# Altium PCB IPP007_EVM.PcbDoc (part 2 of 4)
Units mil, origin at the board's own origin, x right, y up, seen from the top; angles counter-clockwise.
Board outline 3500.95 x 3103 mil, 6 copper layers (Top Layer, Int1 (GND), Int2 (Sign), Int3 (Sign), Int4 (GND), Bottom Layer), stack 61.068 mil thick; 257 components, 132 nets, 1052 pads, 535 vias.
Unrouted connection lines stored in the file: 3.
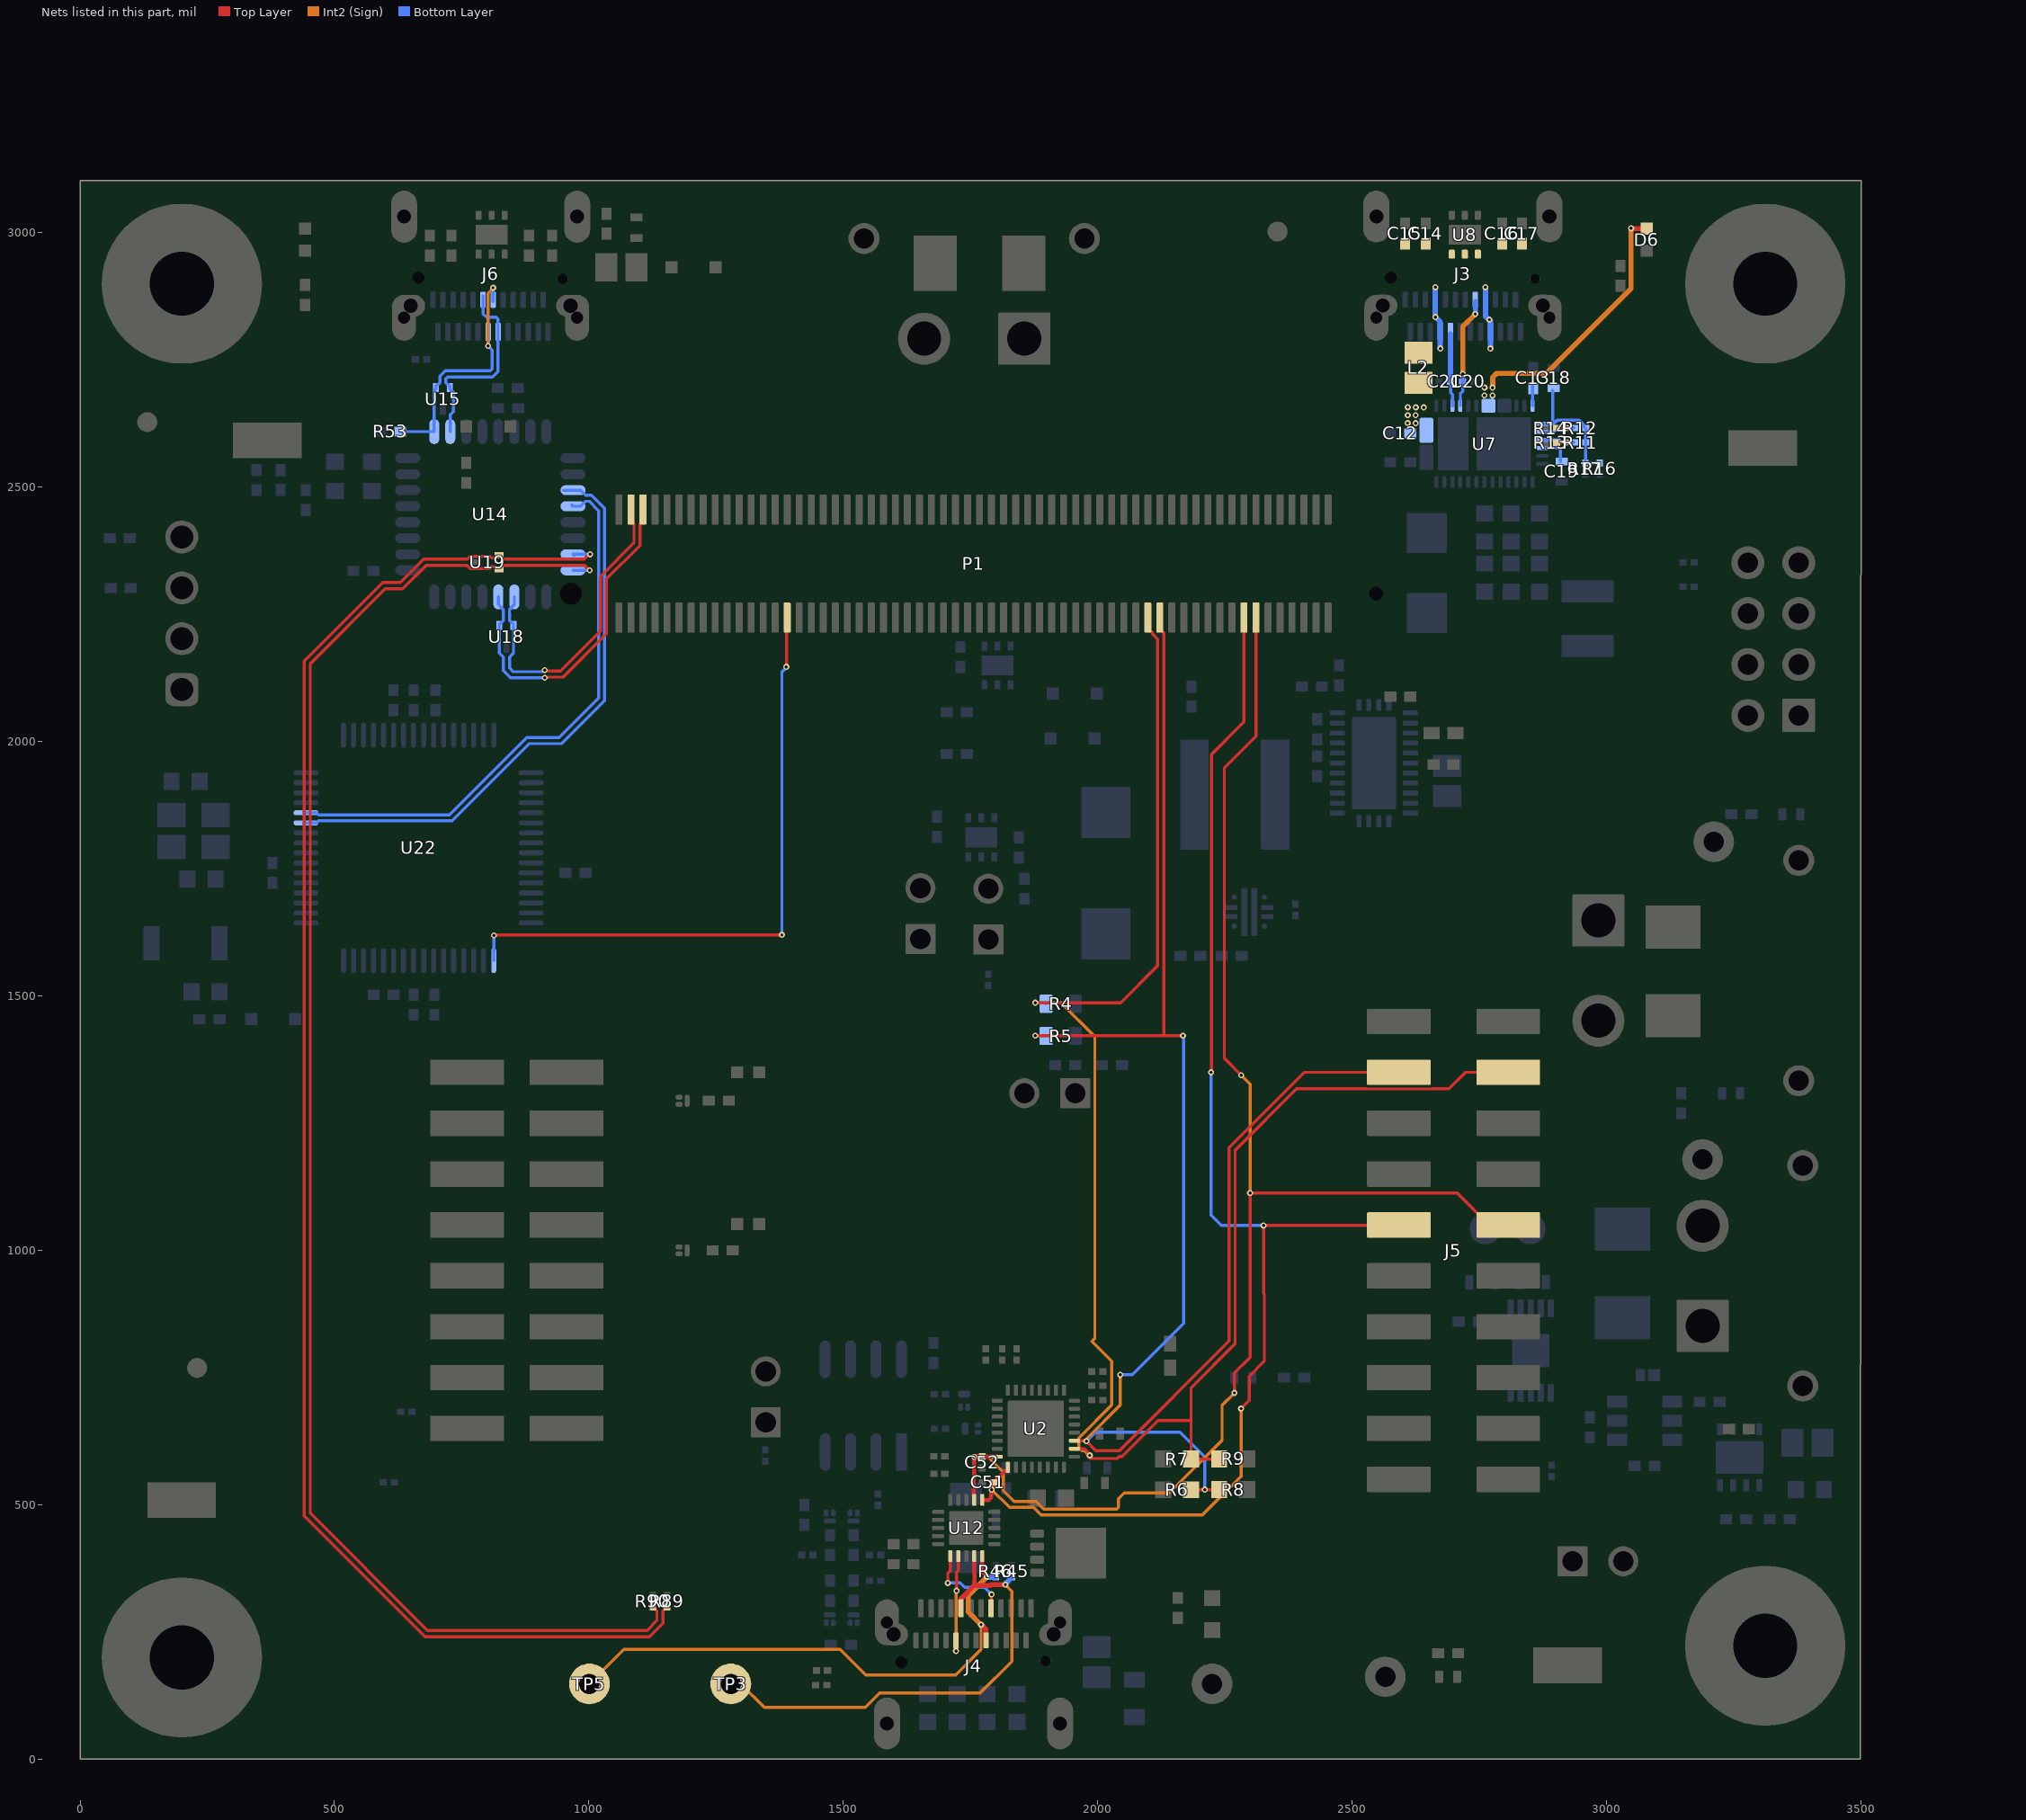
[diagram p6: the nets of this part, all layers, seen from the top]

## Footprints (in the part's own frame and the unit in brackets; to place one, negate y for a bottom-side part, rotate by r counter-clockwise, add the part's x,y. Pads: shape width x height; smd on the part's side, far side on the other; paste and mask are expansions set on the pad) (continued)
WURTH_61300411121 [mm] "Header, 2.54mm, 4x1, TH"
  rrect50% 1.65x1.65 hole 1.15: 1(-3.81,0)
  round 1.65 hole 1.15: 2(-1.27,0) 3(1.27,0) 4(3.81,0)
  body extent -5.08,-1.27 5.08,1.27, height 8.54
XAL6060 [mm] "Coilcraft recommended land pattern Document 887-4 Revised 01/14/18"
  rrect7% 1.43x5.5 smd: 1(-2.019,0) 2(2.019,0)
  body extent -3.28,-3.38 3.28,3.38, height 6.11
YJJ0003A [mm] "SMD, 3-Leads, Body 1x0.6mm"
  rrect80% 0.35x0.25 smd mask-0.05: 1(-0.325,0.175) 2(-0.325,-0.175)
  rrect57% 0.35x0.6 smd mask-0.05: 3(0.325,0)
  silkscreen extent -0.7,0.1 -0.3,0.5, body extent -0.5,-0.3 0.5,0.3, height 0.22
YJM0003A#1 [mm] "SMT, 3-Leads, Body 0.69x0.6mm"
  rrect80% 0.35x0.25 smd paste-0.2 mask-0.05: 1(-0.175,0.175) 2(-0.175,-0.175)
  rrect50% 0.25x0.2 on Top Paste: 1(-0.175,0.2) 2(-0.175,-0.2)
  rrect80% 0.25x0.6 smd paste-0.05 mask-0.05: 3(0.225,0)
  body extent -0.35,-0.3 0.35,0.3, height 0.35
YJM0003A#2 [mm] "SMT, 3-Leads, Body 0.69x0.6mm"
  rrect80% 0.35x0.25 smd paste-0.2 mask-0.05: 1(-0.175,0.175) 2(-0.175,-0.175)
  rrect50% 0.25x0.2 on Bottom Paste: 1(-0.175,0.2) 2(-0.175,-0.2)
  rrect80% 0.25x0.6 smd paste-0.05 mask-0.05: 3(0.225,0)
  body extent -0.35,-0.3 0.35,0.3, height 0.35

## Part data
C1 C2 C5 C6 C35: library part CMP-0006286-2, "CAP, CERM, 1 uF, 16 V, +/- 10%, X6S, 0402", Cap_Case=0402, Manufacturer=TDK, Supplier Part Number 1=445-9086-1-ND, TempCo=X6S, Tolerance_%=10%, Value1="0.011416 ohm", Value2=16V, ValueDisplayed=1uF
C3 C48: library part CMP-0006279-2, "CAP, CERM, 0.1 uF, 50 V, +/- 10%, X5R, 0402", Cap_Case=0402, Manufacturer=TDK, Supplier Part Number 1=445-5942-1-ND, TempCo=X5R, Tolerance_%=10%, Value1="0.039064 ohm", Value2=50V, ValueDisplayed=0.1uF
C4 C7 C9: library part CMP-0006265-2, "CAP, CERM, 3.3 uF, 10 V, +/- 10%, X5R, 0402", Cap_Case=0402, Manufacturer=TDK, Supplier Part Number 1=445-13819-1-ND, TempCo=X5R, Tolerance_%=10%, Value1="0.004157 ohm", Value2=10V, ValueDisplayed=3.3uF
C8: library part CMP-0006277-2, "CAP, CERM, 0.22 uF, 25 V, +/- 20%, X5R, 0402", Cap_Case=0402, Manufacturer=TDK, Supplier Part Number 1=445-5945-1-ND, TempCo=X5R, Tolerance_%=20%, Value1=Unknown, Value2=25V, ValueDisplayed=0.22uF
C12: library part CMP-0006619-2, "CAP, CERM, 1 uF, 35 V, +/- 10%, X5R, 0402", Cap_Case=0402, Manufacturer=MuRata, Supplier Part Number 1=490-10019-1-ND, TempCo=X5R, Tolerance_%=10%, Value1=Unknown, Value2=35V, ValueDisplayed=1uF
C13 C22: library part CMP-0006370-2, "CAP, CERM, 0.1 uF, 35 V, +/- 10%, X5R, 0402", Cap_Case=0402, Manufacturer="Taiyo Yuden", Supplier Part Number 1=587-1994-1-ND, TempCo=X5R, Tolerance_%=10%, Value1=Unknown, Value2=35V, ValueDisplayed=0.1uF
C14 C15 C16 C17 C62 C63 C64 C65: library part CMP-0006236-2, "CAP, CERM, 0.01 uF, 50 V, +/- 5%, X7R, 0402", Cap_Case=0402, Manufacturer=Kemet, Supplier Part Number 1=399-7758-1-ND, TempCo=X7R, Tolerance_%=5%, Value1=Unknown, Value2=50V, ValueDisplayed=0.01uF
C18 C19 C42 C45 C46: library part CMP-0006339-4, "CAP, CERM, 10 uF, 10 V, +/- 20%, X5R, 0402", Cap_Case=0402, Manufacturer="Samsung Electro-Mechanics", TempCo=X5R, Tolerance_%=20%, Value1=Unknown, Value2=10V, ValueDisplayed=10uF
C20 C21: library part CMP-0009653-3, "CAP, CERM, 330 pF, 50 V, +/- 10%, X7R, AEC-Q200 Grade 1, 0201", Cap_Case=0201_033, Manufacturer=TDK, Supplier Part Number 1=445-12111-1-ND, TempCo=X7R, Tolerance_%=10%, Value1="8.05302 ohm", Value2=50V, ValueDisplayed=330pF
C23 C24 C25 C26 C27 C28: library part CMP-0007355-6, "CAP, CERM, 10 uF, 35 V, +/- 20%, X5R, 0603", Cap_Case=0603, Manufacturer=Murata, TempCo=X5R, Tolerance_%=20%, Value1=Unknown, Value2=35V, ValueDisplayed=10uF
C30: library part CMP-0009135-2, "CAP, CERM, 4.7 uF, 100 V, +/- 10%, X7S, 1210", Cap_Case=1210, Manufacturer=TDK, Supplier Part Number 1=445-8912-1-ND, TempCo=X7S, Tolerance_%=10%, Value1=Unknown, Value2=100V, ValueDisplayed=4.7uF
C31: library part CMP-0007895-2, "CAP, CERM, 0.47 uF, 100 V, +/- 10%, X7S, 0805", Cap_Case=0805, Manufacturer=TDK, Supplier Part Number 1=445-5203-1-ND, TempCo=X7S, Tolerance_%=10%, Value1="0.017152 ohm", Value2=100V, ValueDisplayed=0.47uF
C33: library part CMP-0006580-2, "CAP, CERM, 0.47 uF, 10 V, +/- 10%, X5R, 0402", Cap_Case=0402, Manufacturer=MuRata, Supplier Part Number 1=490-3264-1-ND, TempCo=X5R, Tolerance_%=10%, Value1=Unknown, Value2=10V, ValueDisplayed=0.47uF
C34: library part CMP-0011955-2, "CAP, TA, 220 uF, 16 V, +/- 20%, 0.1 ohm, SMD", Cap_Case=E, Manufacturer=AVX, Supplier Part Number 1=478-4131-1-ND, Tolerance_%=20%, Value1="0.1 ohm", Value2=16V, ValueDisplayed=220uF
C36: library part CMP-0006288-2, "CAP, CERM, 2.2 uF, 16 V, +/- 10%, X6S, 0402", Cap_Case=0402_065, Manufacturer=TDK, Supplier Part Number 1=445-9103-1-ND, TempCo=X6S, Tolerance_%=10%, Value1="0.005925 ohm", Value2=16V, ValueDisplayed=2.2uF
C37: library part CMP-0098058-1, "4.7 µF ±10% 100V Ceramic Capacitor X5R 0805 (2012 Metric)", Digikey Part Number=445-C2012X5R2A475K125ACCT-ND, Manufacturer=TDK, Mouser Part Number=810-C2012X5R2A475K12, Operating Temperature Range="-55°C to +85°C", TempCo=15%, Temperature Characteristic=X5R, Tolerance_%=10%, ValueDisplayed=4.7uF
C38 C39 C40 C41: library part CMP-0006977-4, "CAP, CERM, 0.01 uF, 100 V, +/- 10%, X7R, 0603", Cap_Case=0603, Manufacturer=Kemet, Supplier Part Number 1=399-5347-1-ND, TempCo=X7R, Tolerance_%=10%, Value1=Unknown, Value2=100V, ValueDisplayed=0.01uF
C43 C44: library part CMP-0007344-5, "CAP, CERM, 10 uF, 25 V, +/- 20%, X5R, 0603", Cap_Case=0603, Manufacturer=MuRata, Supplier Part Number 1=490-7202-1-ND, TempCo=X5R, Tolerance_%=20%, Value1=Unknown, Value2=25V, ValueDisplayed=10uF
C47: library part CMP-0006618-2, "CAP, CERM, 0.1 uF, 100 V, +/- 10%, X5R, 0402", Cap_Case=0402, Manufacturer=MuRata, Supplier Part Number 1=490-10458-1-ND, TempCo=X5R, Tolerance_%=10%, Value1=Unknown, Value2=100V, ValueDisplayed=0.1uF
C49: library part CMP-0009692-3, "CAP, CERM, 1 uF, 6.3 V, +/- 20%, X5R, 0201", Cap_Case=0201, Manufacturer=MuRata, Supplier Part Number 1=490-7229-1-ND, TempCo=X5R, Tolerance_%=20%, Value1=Unknown, Value2=6.3V, ValueDisplayed=1uF
C50: library part CMP-0008716-2, "CAP, CERM, 0.47 uF, 100 V, +/- 10%, X7R, 1206", Cap_Case=1206_180, Manufacturer=TDK, Supplier Part Number 1=445-2284-1-ND, TempCo=X7R, Tolerance_%=10%, Value1="0.007558 ohm", Value2=100V, ValueDisplayed=0.47uF
C51 C52: library part CMP-0009652-3, "CAP, CERM, 220 pF, 50 V, +/- 10%, X7R, AEC-Q200 Grade 1, 0201", Cap_Case=0201_033, Manufacturer=TDK, Supplier Part Number 1=445-12109-1-ND, TempCo=X7R, Tolerance_%=10%, Value1="11.6275 ohm", Value2=50V, ValueDisplayed=220pF
C53 C61 C82 C83 C84 C86 C88: library part CMP-0006325-2, "CAP, CERM, 0.1 uF, 50 V, +/- 10%, X7R, AEC-Q200 Grade 1, 0402", Cap_Case=0402, Manufacturer=TDK, Supplier Part Number 1=445-6899-1-ND, TempCo=X7R, Tolerance_%=10%, Value1="0.039064 ohm", Value2=50V, ValueDisplayed=0.1uF
C54 C55 C56 C57: library part CMP-0006531-2, "CAP, CERM, 0.1 uF, 6.3 V, +/- 10%, X5R, 0402", Cap_Case=0402, Manufacturer=MuRata, Supplier Part Number 1=GRM155R60J104KA01D-ND, TempCo=X5R, Tolerance_%=10%, Value1=Unknown, Value2=6.3V, ValueDisplayed=0.1uF
C58: library part CMP-0078623-1, "CAP, CERM, 10 µF, 10 V,+/- 20%, X5R, 0402", Cap_Case=0402_080, Manufacturer=AVX, Supplier Part Number 1=478-10052-1-ND, TempCo=X5R, Tolerance_%=20%, Value2=10V, ValueDisplayed=10µF
C59: library part CMP-0750059-1, "CAP, CERM, 1 µF, 100 V,+/- 10%, X7S, 0805", Cap_Case=0805, Manufacturer=TDK, TempCo=X7S, Tolerance_%=10%, Value2=100V, ValueDisplayed=1µF
C60: library part CMP-0007499-4, "CAP, CERM, 2.2 uF, 16 V, +/- 10%, X7R, 0603", Cap_Case=0603, Manufacturer=MuRata, Supplier Part Number 1=81-GRM188Z71C225KE3D, TempCo=X7R, Tolerance_%=10%, Value1=Unknown, Value2=16V, ValueDisplayed=2.2uF
C66: library part CMP-0081457-1, "CAP, CERM, 1 µF, 10 V,+/- 20%, X5R, 0402", Cap_Case=0402, Manufacturer="Yageo America", TempCo=X5R, Tolerance_%=20%, Value2=10V, ValueDisplayed=1µF
C85 C87: library part CMP-0006269-2, "CAP, CERM, 4.7 uF, 10 V, +/- 20%, X5R, 0402", Cap_Case=0402, Manufacturer=TDK, Supplier Part Number 1=445-8023-1-ND, TempCo=X5R, Tolerance_%=20%, Value1=Unknown, Value2=10V, ValueDisplayed=4.7uF
C89: library part CMP-0006770-4, "CAP, CERM, 180 pF, 50 V, +/- 5%, C0G/NP0, 0603", Cap_Case=0603, Manufacturer=AVX, Supplier Part Number 1=478-1178-1-ND, TempCo=C0G/NP0, Tolerance_%=5%, Value1="0.09 ohm", Value2=50V, ValueDisplayed=180pF
C90 C91: library part CMP-0006761-4, "CAP, CERM, 10 pF, 50 V, +/- 5%, C0G/NP0, 0603", Cap_Case=0603, Manufacturer=AVX, Supplier Part Number 1=478-1163-1-ND, TempCo=C0G/NP0, Tolerance_%=5%, Value1="0.403 ohm", Value2=50V, ValueDisplayed=10pF
D1: library part CMP-0067542-2, "Diode, Schottky, 60 V, 5 A, SMA", Manufacturer="Micro Commercial Components", Value1=5A, Value2=0.75V
D2 D5 D10: library part CMP-0028447-2, "Diode, Schottky, 30 V, 0.2 A, SOD-323", Manufacturer="Diodes Inc.", Value1=0.2A, Value2=1V
D3 D20 D22: library part CMP-0005570-3, "Diode, TVS, Uni, 48 V, 77.4 Vc, SMB", Manufacturer="Diodes Inc.", Value1=600W
D4 D6 D23 D26: library part CMP-0002919-2, "LED, White, SMD", Color=White, Manufacturer=OSRAM, Value1=W, Value2=2.8V
D7: library part CMP-0002946-3, "LED, Blue, SMD", Color=Blue, Manufacturer="Wurth Elektronik", Power_TotalModule=105mW, Value1=0.105W, Value2=3.2V
D8: library part CMP-0076922-2, "Diode, Schottky, 5 V, 0.03 A, SOD-323", Manufacturer=Toshiba, Value1=0.03A, Value2=0.38V
D12: library part CMP-0077002-2, "Diode, Schottky, 30 V, 0.5 A, 0402 Diode", Manufacturer="ON Semiconductor", Value1=0.5A, Value2=0.43V
D13: library part CMP-0028852-2, "Diode, Schottky, 10 V, 3 A, SOD-323F", Manufacturer=Nexperia, Value1=3A, Value2=0.53V
FID1 FID2 FID3: library part CMP-0077181-1, "Fiducial mark.  There is nothing to buy or mount.", Manufacturer=N/A
H1 H2 H3 H4: library part CMP-0003617-1, "Machine Screw, Round, #4-40 x 1/4, Nylon, Philips panhead", Manufacturer="B&F Fastener Supply", Supplier Part Number 1=H542-ND
H5 H6 H7 H8: library part CMP-0003610-1, "Standoff, Hex, 0.5\"L #4-40 Nylon", Manufacturer=Keystone, Supplier Part Number 1=36-1902C-ND
J1: library part CMP-0121007-1, "Socket, DC supply, XT30, male, PIN: 2, on PCBs, THT, yellow, 15A, 500V", Current_A=15A, Manufacturer=Amass, Operating Temperature Range="-20°C to +120°C", Voltage_V=500V
J2: library part CMP-0075595-1, "Header, 2.54mm, 8x2, Gold, SMT", Color=Black, Current_A=4.9A, Manufacturer=Samtec, Supplier Part Number 1=SAM8884-ND, Voltage_V=475V
J3 J4 J6: library part CMP-0085712-2, "Receptacle, USB 3.1 Type C, R/A, Gold, SMT", Color=Black, Current_A=1.25A, Manufacturer="JAE Electronics", Voltage_V=20V
J5: library part CMP-0077452-1, "Header, 2.54mm, 10x2, Tin, SMT", Color=Black, Manufacturer=FCI, Supplier Part Number 1=54202-G0810LF-ND, Voltage_V=1.5kV
J7 J8: library part CMP-0035193-3, "Socket, DC supply, XT30, female, PIN: 2, on PCBs, THT, yellow, 15A", Current_A=15A, Manufacturer=Amass, Operating Temperature Range="-20°C to +120°C", Voltage_V=500V
J9: library part CMP-0075408-3, "Header, 100mil, 4x2, Gold, TH", Color=Black, Current_A=6.3A, Manufacturer=Samtec, Supplier Part Number 1=SAM1028-04-ND, Voltage_V=550V
J10: library part CMP-0054798-2, "Header, 2.54 mm, 4x1, Gold, TH", Color=Black, Manufacturer="Wurth Elektronik", Supplier Part Number 1=732-5317-ND
J11 J12 J13 J14 J15: library part CMP-0002337-1, "Header, 100mil, 2x1, Tin, TH", Color=Black, Current_A=3A, Manufacturer="Sullins Connector Solutions", Supplier Part Number 1=S1012E-02-ND, Voltage_V=1.8kV
L2 L4 L5: library part CMP-0003072-1, "Ferrite Bead, 22 ohm @ 100 MHz, 6 A, 0805", Manufacturer="Wurth Elektronik", Supplier Part Number 1=732-4637-1-ND, Value1="0.008 ohm", Value2=6A, ValueDisplayed="22 ohm"
L3: library part CMP-0061020-2, "Inductor, Shielded, Composite, 4.7 µH, 10.5 A, 0.0144 ohm, AEC-Q200 Grade 1, SMD", Manufacturer=Coilcraft, Value1="0.0144 ohm", Value2=10.5A, ValueDisplayed=4.7uH
LBL1: library part CMP-0003625-1, "Thermal Transfer Printable Labels, 0.650\" W x 0.200\" H - 10,000 per roll", Manufacturer=Brady, Supplier Part Number 1=97C5133
Logo1: library part CMP-0074844-1
Logo2: library part CMP-0074838-1, "Texas Instrument Corporate Signature"
Logo3: library part CMP-0074847-1, "FCC_disclaimer"
Logo4: library part CMP-0074769-3, Manufacturer="Texas Instruments"
P1: library part CMP-0055794-1, "Header(shrouded), 0.6mm, 60x2, Gold, SMT", Current_A=400mA, Manufacturer="Hirose Electric Co. Ltd.", Supplier Part Number 1=H10695-ND, Voltage_V=100V
Q3: library part CMP-0120201-1, "Mosfet Array 80V 30A (Tc) 48W Surface Mount PowerPAK® SO-8 Dual", Digikey Part Number=SQJB80EP-T1_GE3CT-ND, Drain To Source Breakdown Voltage=80V, Input Capacitace At Vds="1015pF @ 25V", Manufacturer=Vishay, Mouser Part Number=78-SQJB80EP-T1_GE3, Operating Temperature Range="-55°C to +175°C", Power_W=48W, Pulse Drain Current=84A, Typ Forward Diode Voltage=0.84V
Q6 Q7: library part CMP-0000571-1, "MOSFET, N-CH, 30 V, 3 A, YJJ0003A (PICOSTAR-3)", Alternate Manufacturer=None, Manufacturer="Texas Instruments", Supplier Part Number 1=296-42130-1-ND, Value1=0.12, Value2="0.92 nC"
Q8: library part CMP-0079500-2, "MOSFET, N-CH, 30 V, 60 A, DNH0008A (VSONP-8)", Alternate Manufacturer=None, Manufacturer="Texas Instruments", Supplier Part Number 1=CSD17581Q3A-ND, Value1="0.0047 ohm", Value2="20 nC"
Q15 Q18 QN1 QN2: library part CMP-0000206-2, "MOSFET, N-CH, 20 V, 0.5 A, YJM0003A (PICOSTAR-3)", Alternate Manufacturer=None, Manufacturer="Texas Instruments", Supplier Part Number 1=296-44373-1-ND, Value1=1.4, Value2="0.216 nC"
QP1 QP2: library part CMP-0000027-4, "MOSFET, P-CH, -20 V, -1.7 A, YJM0003A (PICOSTAR-3)", Alternate Manufacturer=None, Manufacturer="Texas Instruments", Value1=0.15, Value2="0.7 nC"
R1 R18 R21 R22 R58 R79 R80 R94 R95: library part CMP-0025950-3, "RES, 100 k, 1%, 0.063 W, AEC-Q200 Grade 0, 0402", Manufacturer=Vishay-Dale, Power_W=63mW, Supplier Part Number 1=541-100KLCT-ND, TempCo="100 ppm/C", Tolerance_%=1%, Value2=0.063W, Value_Code=100k
R2: library part CMP-0026659-2, "RES, 100 k, 1%, 0.1 W, 0402", Manufacturer=Panasonic, Power_W=100mW, TempCo="100 ppm/C", Tolerance_%=1%, Value2=0.1W, Value_Code=100k
R3 R15 R56 R60 R67 R93 R149 R152: library part CMP-0026825-5, "RES, 10 k, 5%, 0.063 W, AEC-Q200 Grade 0, 0402", Manufacturer=Vishay-Dale, Power_W=63mW, Supplier Part Number 1=541-10KJCT-ND, TempCo="200 ppm/C", Tolerance_%=5%, Value2=0.063W, Value_Code=10k0, ValueDisplayed=10k
R4 R5: library part CMP-0097467-1, "0 Ohms Jumper 0.125W, 1/8W Chip Resistor 0603 (1608 Metric) Automotive AEC-Q200 Thick Film", Digikey Part Number=10-ERJ-H3G0R00VCT-ND, Manufacturer=Panasonic, Mouser Part Number=667-ERJ-H3G0R00V, Operating Temperature Range="-55°C to +175°C", Power_W=125mW
R6 R7 R8 R9: library part CMP-0022735-5, "RES, 100 k, 1%, 0.1 W, 0603", Manufacturer=Yageo, Power_W=100mW, Supplier Part Number 1=311-100KHRCT-ND, TempCo="100 ppm/C", Tolerance_%=1%, Value2=0.1W, Value_Code=100k
R10: library part CMP-0028071-1, "RES, 10.0 k, 1%, 0.05 W, 0201", Manufacturer="Yageo America", Power_W=50mW, Supplier Part Number 1=603-RC0201FS-7D10KL, TempCo="200 ppm/C", Tolerance_%=1%, Value2=0.05W, Value_Code=10k0, ValueDisplayed=10.0k
R11 R12: library part CMP-0078704-2, "RES, 200 k, 1%, 0.05 W, 0201", Manufacturer=Vishay-Dale, Power_W=50mW, Supplier Part Number 1=541-200KAABCT-ND, TempCo="100 ppm/C", Tolerance_%=1%, Value2=0.05W, Value_Code=200k
R13 R14: library part CMP-0027757-1, "RES, 51.0 k, 1%, 0.05 W, 0201", Manufacturer="Yageo America", Power_W=50mW, Supplier Part Number 1=311-51.0KMCT-ND, TempCo="200 ppm/C", Tolerance_%=1%, Value2=0.05W, Value_Code=51k0, ValueDisplayed=51.0k
R16 R17 R36 R37 R42 R43: library part CMP-0027272-3, "RES, 2.20 k, 1%, 0.05 W, 0201", Manufacturer=Vishay-Dale, Power_W=50mW, Supplier Part Number 1=541-2.20KAABCT-ND, TempCo="100 ppm/C", Tolerance_%=1%, Value2=0.05W, Value_Code=2k20, ValueDisplayed=2.20k
R19 R29 R38 R44 R59: library part CMP-0027262-3, "RES, 10.0 k, 1%, 0.05 W, 0201", Manufacturer=Vishay-Dale, Power_W=50mW, Supplier Part Number 1=541-10.0KAABCT-ND, TempCo="100 ppm/C", Tolerance_%=1%, Value2=0.05W, Value_Code=10k0, ValueDisplayed=10.0k
R20: library part CMP-0026369-2, "RES, 412 k, 1%, 0.063 W, AEC-Q200 Grade 0, 0402", Manufacturer=Vishay-Dale, Power_W=63mW, Supplier Part Number 1=541-412KLCT-ND, TempCo="100 ppm/C", Tolerance_%=1%, Value2=0.063W, Value_Code=412k
R23: library part CMP-0026683-1, "RES, 23.7 k, 1%, 0.1 W, AEC-Q200 Grade 0, 0402", Manufacturer=Panasonic, Power_W=100mW, Supplier Part Number 1=P23.7KLCT-ND, TempCo="100 ppm/C", Tolerance_%=1%, Value2=0.1W, Value_Code=23k7, ValueDisplayed=23.7k
R24 R25 R26 R27 R28 R30 R45 R46 R77 R78 R89 R90 R137 R139: library part CMP-0027008-4, "RES, 0, 5%, 0.05 W, 0201", Manufacturer=Vishay-Dale, Power_W=50mW, Supplier Part Number 1=72M6743, TempCo=ppm/C, Tolerance_%=5%, Value2=0.05W, Value_Code=0000, ValueDisplayed=0
R31: library part CMP-0026822-1, "RES, 0, 5%, 0.063 W, 0402", Manufacturer=Vishay-Dale, Power_W=63mW, Supplier Part Number 1=541-0.0JCT-ND, TempCo="200 ppm/C", Tolerance_%=5%, Value2=0.063W, Value_Code=0000, ValueDisplayed=0
R32 R96 R97 R98: library part CMP-0025958-3, "RES, 10.0 k, 1%, 0.063 W, AEC-Q200 Grade 0, 0402", Manufacturer=Vishay-Dale, Power_W=63mW, Supplier Part Number 1=541-10.0KLCT-ND, TempCo="100 ppm/C", Tolerance_%=1%, Value2=0.063W, Value_Code=10k0, ValueDisplayed=10.0k
R34 R35: library part CMP-0027293-2, "RES, 100 k, 1%, 0.05 W, 0201", Manufacturer="Yageo America", Power_W=50mW, Supplier Part Number 1=311-100KMCT-ND, TempCo="200 ppm/C", Tolerance_%=1%, Value2=0.05W, Value_Code=100k
R47 R52: library part CMP-0026745-1, "RES, 100 k, 1%, 0.063 W, 0402", Manufacturer="Samsung Electro-Mechanics", Power_W=63mW, Supplier Part Number 1=1276-3432-1-ND, TempCo="100 ppm/C", Tolerance_%=1%, Value2=0.063W, Value_Code=100k
R48 R49 R50 R51: library part CMP-0026660-1, "RES, 1.00 M, 1%, 0.1 W, 0402", Manufacturer=Panasonic, Power_W=100mW, Supplier Part Number 1=P1.00MLCT-ND, TempCo="100 ppm/C", Tolerance_%=1%, Value2=0.1W, Value_Code=1M00, ValueDisplayed=1.00M
R53: library part CMP-0026756-1, "RES, 1.50 k, 1%, 0.063 W, AEC-Q200 Grade 0, 0402", Manufacturer="Stackpole Electronics Inc", Power_W=63mW, Supplier Part Number 1=RMCF0402FT1K50CT-ND, TempCo="100 ppm/C", Tolerance_%=1%, Value2=0.063W, Value_Code=1k50, ValueDisplayed=1.50k
R54 R55: library part CMP-0027789-1, "RES, 5.10 k, 1%, 0.05 W, 0201", Manufacturer="Yageo America", Power_W=50mW, Supplier Part Number 1=YAG2741CT-ND, TempCo="200 ppm/C", Tolerance_%=1%, Value2=0.05W, Value_Code=5k10, ValueDisplayed=5.10k
R63: library part CMP-0077551-1, "RES, 115 k, 1%, 0.063 W, 0402", Manufacturer="Yageo America", Power_W=63mW, Supplier Part Number 1=YAG2956CT-ND, TempCo="100 ppm/C", Tolerance_%=1%, Value2=0.063W, Value_Code=115k
R65 R66 R71 R72: library part CMP-0026605-2, "RES, 90.9 k, 1%, 0.063 W, AEC-Q200 Grade 0, 0402", Manufacturer=Vishay-Dale, Power_W=63mW, Supplier Part Number 1=541-90.9KLCT-ND, TempCo="100 ppm/C", Tolerance_%=1%, Value2=0.063W, Value_Code=90k9, ValueDisplayed=90.9k
R69 R70 R73 R74: library part CMP-0094735-1, "10 kOhms ±1% 0.063W, 1/16W Chip Resistor 0402 (1005 Metric)  Thick Film", Digikey Part Number=541-3959-1-ND, Manufacturer=Vishay, Mouser Part Number=71-CRCW040210K0FKEDC, Operating Temperature Range="-55°C to +155°C", Power_W=63mW, TempCo=100ppm/°C, Tolerance_%=1%
R81: library part CMP-0027865-1, "RES, 750, 1%, 0.05 W, 0201", Manufacturer="Yageo America", Power_W=50mW, Supplier Part Number 1=YAG2794CT-ND, TempCo="200 ppm/C", Tolerance_%=1%, Value2=0.05W, Value_Code=750R, ValueDisplayed=750
R91: library part CMP-0028069-1, "RES, 100 k, 1%, 0.05 W, 0201", Manufacturer="Yageo America", Power_W=50mW, Supplier Part Number 1=603-RC0201FS-7D100KL, TempCo="200 ppm/C", Tolerance_%=1%, Value2=0.05W, Value_Code=100k
S2: library part CMP-0002150-2, "SWITCH TACTILE SPST-NO 0.05A 12V", CurrentRating_mA=50A, Manufacturer="Omron Electronic Components", Supplier Part Number 1=SW1020CT-ND
SH-J11 SH-J12 SH-J13 SH-J14 SH-J15: library part CMP-0003623-3, "Shunt, 100mil, Gold plated, Black", Alternate Manufacturer=3M, Alternate PartNumber=969102-0000-DA, Manufacturer=Samtec, Supplier Part Number 1=SAM8858-ND
TP1 TP11: library part CMP-0055140-2, "Test Point, Miniature, Orange, TH", Color=Orange, Manufacturer="Keystone Electronics", Supplier Part Number 1=36-5003-ND
TP2: library part CMP-0055154-1, "Test Point, Miniature, Blue, TH", Color=Blue, Manufacturer=Keystone, Supplier Part Number 1=36-5117-ND
TP3 TP5: library part CMP-0055139-2, "Test Point, Miniature, White, TH", Color=White, Manufacturer="Keystone Electronics", Supplier Part Number 1=36-5002-ND
TP4: library part CMP-0055137-2, "Test Point, Miniature, Red, TH", Color=Red, Manufacturer="Keystone Electronics", Supplier Part Number 1=36-5000-ND
TP7 TP10 TP13 TP14: library part CMP-0055152-2, "Test Point, Miniature, SMT", Manufacturer="Keystone Electronics", Supplier Part Number 1=36-5015TR-ND
U1 U3: library part CMP-0074651-9, "1A Low-Quiescent-Current Low-Dropout (LDO) Regulator, DRV0006A (WSON-6)", Alternate Manufacturer="Texas Instruments", Operating Temperature Range="-40 to 125 C", Rating=Catalog
U2: library part CMP-0121143-2, "USB Type-C® and USB PD Controller with Integrated Power Switches Optimized for Power Applications", Manufacturer="Texas Instruments", Max Supply Voltage=22V, Min Supply Voltage=3V, Nominal Supply Current=1-3mA, Operating Temperature Range="-40°C to +125°C"
U4: library part CMP-0093419-2, "2.7- 16 V, 10 A, 7 mΩ eFuse with transient overcurrent blanking timer", Manufacturer="Texas Instruments", Max Supply Voltage=16V, Min Supply Voltage=2.7V, Nominal Supply Current=430uA, Operating Temperature Range="-40°C to +125°C", Output Voltage=0-16V
U6: library part CMP-0072086-1, "Switched Capacitor Voltage Converter, 6-pin SOT-23, Pb-Free", Manufacturer="Texas Instruments", PackageTopMarking=S15B*XTT, PowerWise=N
U7: library part CMP-0090338-5, "USB Type-C and USB PD Controller with Integrated Power Switches Optimized for Power Applications", Manufacturer="Texas Instruments", Max Supply Voltage=22V, Min Supply Voltage=3V, Operating Temperature Range="-40°C to +125°C"
U8: library part CMP-0077834-1, "22-V Precision Surge Protection Clamp, DRV0006A (WSON-6)", Alternate Manufacturer="Texas Instruments"
U9: library part CMP-0861019-1, "3.5V to 60V 5A Synchronous Step-Down Voltage Regulator, RNP0030A (WQFN-30)", Alternate Manufacturer="Texas Instruments"
U10: library part CMP-0120203-2, "High-Side Gate Driver IC Non-Inverting 10-MSOP-EP", Digikey Part Number=LTC7004IMSE#TRPBFCT-ND, Manufacturer="Analog Devices", Max Supply Voltage=15V, Min Supply Voltage=3.5V, Mouser Part Number=584-7004IMSETRPBF, Nominal Supply Current=225uA, Operating Temperature Range="-40°C to +125°C"
U12: library part CMP-0034161-1, "USB Type-C® 48V EPR Port Protector: Short-to-VBUS Overvoltage and IEC ESD Protection", Manufacturer="Texas Instruments", Operating Supply Voltage=3.3V, Operating Temperature Range="-40°C to +125°C"
U13: library part CMP-0091847-1, "EEPROM Memory IC 512Kb (64K x 8) I²C 1MHz 900ns 8-SOIC", Digikey Part Number=CAT24C512WI-GT3OSCT-ND, Frequency_Fixed=1MHz, Manufacturer="ON Semi", Max Supply Voltage=5.5V, Min Supply Voltage=1.8V, Mouser Part Number=863-CAT24C512WI-GT3, Operating Temperature Range="-40°C to +85°C"
U14: library part CMP-0033740-1, "2 / 3-Port Hub for USB with Optional Serial EEPROM Interface, 3.3V, 0 to 70 degC, 32-Pin LQFP (VF), Green (RoHS & no Sb/Br)", Manufacturer="Texas Instruments", Supply Voltage(s)(V)=3.3
U15 U18 U19: library part CMP-0043104-2, "ESD Solution for Super-Speed (6 Gbps) USB 3.0 Interface, 2 Channels, -40 to +85 degC, 3-pin SOT (DRT), Green (Rohs & No Sb/Br)", Breakdown Voltage(Min)(V)=9, Differential Capacitance(pF)=0.01, IO Capacitance(Typ)(pF)=0.7, IO Leakage Current(nA)=10, Manufacturer="Texas Instruments"
U17: library part CMP-0077837-1, "5-V Precision Surge Protection Clamp, DRV0006A (WSON-6)", Alternate Manufacturer="Texas Instruments"
U20: library part CMP-0079946-1, "60V, 5uA Iq, 100mA Low-Dropout (LDO) Voltage Regulator With Enable and Power Good, DRB0008B (VSON-8)", Alternate Manufacturer="Texas Instruments", Alternate PartNumber=TPS7A1650DRBT
U22: library part CMP-0029860-3, "Tiva C Series Microcontroller, 256 KB Flash, 32 KB SRAM, 12 Bit, 12 Channels, -40 to 105 degC, 64-Pin LQFP (PM), Green (RoHS & no Sb/Br), Tape and Reel", Manufacturer="Texas Instruments", Temperature Range="-40 to 105 degC"
Y1: library part CMP-0121117-1, "Oscillator XO 48MHz ±50ppm 15pF HCMOS 55% 1.8V/2.5V/3.3V 4-Pin Mini-CSMD T/R", Digikey Part Number=XC2756CT-ND, Frequency Stability=50ppm, Frequency_Fixed=48MHz, Load Capacitance=15pF, Manufacturer="ECS International", Max Supply Current=8mA, Max Supply Voltage=3.6V, Min Supply Voltage=1.6V, Mouser Part Number=520-2520MV-480-BN-T, Operating Temperature Range="-40°C to +85°C"
Y2: library part CMP-0004635-3, "Crystal, 16 MHz, 8pF, SMD", Frequency Stability=+/-30ppm, Frequency_Fixed=16MHz, Manufacturer=NDK, Supplier Part Number 1=644-1157-1-ND
ZZ1: library part CMP-0003616-3
ZZ2: library part CMP-0077236-1
ZZ3: library part CMP-0077237-1
ZZ4: library part CMP-0077238-1
ZZ5: library part CMP-0077238-1, "These assemblies must comply with workmanship standards IPC-A-610 Class 2, unless otherwise specified."

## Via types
v1: diameter 12, hole 6, Top Layer to Bottom Layer, tented both sides, 471 vias
v2: diameter 19.68, hole 7.87, Top Layer to Bottom Layer, tented both sides, 34 vias
v3: diameter 23.62, hole 11.81, Top Layer to Bottom Layer, 24 vias
v4: diameter 19.68, hole 7.87, Top Layer to Bottom Layer, 6 vias

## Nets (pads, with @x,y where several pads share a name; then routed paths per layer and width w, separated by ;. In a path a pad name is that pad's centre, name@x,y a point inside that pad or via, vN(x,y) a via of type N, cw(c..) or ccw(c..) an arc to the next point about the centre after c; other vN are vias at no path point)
730_ADC1: R12.1 R14.2 U7.2 | length 100.7
  Top Layer w6: R14.2@2901.63,2616.26 2901.73,2616.36 2922.18,2616.36 v1(2922.24,2616.42) v1@2923.11,2617.29
  Bottom Layer w6: U7.2@2874.29,2608.86 2897.32,2608.86 2904.88,2616.42 ; 2904.99,2616.53 R12.1@2936.22,2616.53 ; v1@2922.42,2616.55 R12.1@2936.2,2616.55
730_ADC2: R11.1 R13.2 U7.3 | length 85.9
  Top Layer w6: R13.2@2901.63,2587.57 2901.81,2587.75 2922.1,2587.75 v1(2922.28,2587.93) v1@2923.52,2587.93
  Bottom Layer w6: U7.3@2874.29,2593.11 2907.6,2593.11 2912.6,2588.11 ; 2912.71,2588.22 R11.1@2936.22,2588.22
730_CC1: C21.1 J3.A5 U7.28 | length 143.3
  Bottom Layer w6: J3.A5@2693.23,2801.76 J3.A5@2693.41,2801.57 ; C21.1@2693.41,2707.79 C21.1@2693.59,2707.61 2693.59,2685.93 2697.12,2682.4 U7.28@2697.12,2660.04
  Bottom Layer w10: C21.1@2693.41,2707.79 J3.A5@2693.41,2801.57
730_CC2: C20.1 J3.B5 U7.29 | length 216.9
  Int2 (Sign) w10: v1(2717.62,2722.68) 2717.62,2815.73 v1(2742.15,2840.27)
  Bottom Layer w6: U7.29@2712.87,2660.04 2712.87,2683.96 2717.7,2688.79 C20.1@2717.7,2707.61 C20.1@2717.62,2707.69 ; v1(2717.62,2722.68) v1(2717.62,2722.68) ; v1@2742.3,2840.7 v1@2742.44,2840.55 ; J3.B5@2742.3,2864.61 J3.B5@2742.44,2864.75
  Bottom Layer w10: C20.1@2717.62,2707.69 v1(2717.62,2722.68) ; v1@2742.3,2840.7 J3.B5@2742.3,2864.61
730_LDO_1V5: C19.2 U7.4 | length 59.4
  Bottom Layer w6: U7.4@2874.29,2577.36 2905.74,2577.36 2909.26,2573.85 C19.2@2909.26,2550.89
730_LDO_3V3: C18.2 R11.2 R12.2 R16.1 R17.1 U7.1 | length 255.8
  Bottom Layer w6: U7.1@2874.29,2624.6 2894.53,2624.6 C18.2@2894.53,2689.89 ; 2896.09,2624.6 2902.95,2631.46 ; 2903.06,2631.57 2946.18,2631.57 2955.07,2622.69 2955.07,2619.67 2958.85,2615.89 2958.85,2548.11 R17.1@2958.54,2547.8 R16.1@2986.86,2547.8
730_VBUS: C14.1 C15.1 C16.1 C17.1 J3.A4 J3.A9 J3.B4 J3.B9 L2.1 U8.4 U8.5 U8.6 | length 246.6
  Bottom Layer w10.5: J3.B9@2663.7,2863.14 2663.7,2834.73 2673.54,2824.89 2673.28,2801.76 J3.A4@2673.27,2800.15 ; J3.B9@2663.7,2864.75 v1(2663.7,2893.16) ; v1(2673.54,2772.65) J3.A4@2673.54,2800.15 ; J3.B4@2762.12,2863.14 2762.12,2836.16 2768.68,2829.6 2769.71,2829.6 v1(2770,2829.31) 2770,2828.91 2771.9,2827.01 2771.9,2801.82 2771.97,2801.76 2771.97,2800.15 v1(2771.97,2772.65) ; J3.B4@2762.12,2864.75 v1(2762.12,2893.16)
  other v1: 2663.75,2834.42
730_VBUS_C: C12.1 D6.1 L2.2 U7.23 U7.24 U7.25 U7.32 U7.33 U7.@2645.94,2611.87 U7.@2767.99,2660.04 | length 514
  Top Layer w10: v1(3048.49,3008.93) 3049.04,3008.93 3049.69,3008.28 D6.1@3079.1,3008.28
  Int2 (Sign) w10: v1(2776.11,2695.78) 2776.49,2696.17 2776.49,2716.33 2783.97,2723.81 2881.56,2723.81 3048.49,2890.74 v1(3048.49,3008.93)
  other v1: 2609.32,2626.07 2624.9,2625.92 2625.05,2641.51 2609.47,2641.66 2609.61,2657.24 2625.2,2657.09 2640.78,2656.95 2760.38,2680.35 2775.96,2680.2 2760.52,2695.93
730_VIN_3V3: C13.1 U7.38 | length 39.4
  Bottom Layer w6: U7.38@2854.6,2660.04 C13.1@2854.6,2699.46
ADCIN1: J5.B02 P1.89 R4.1 R7.1 R9.2 U2.2 | length 3589.9
  Top Layer w6: v1(1877.2,1486.88) 1877.24,1486.84 2045.2,1486.84 2117.88,1559.52 2117.88,2201.87 2107.6,2212.15 2107.6,2213.66 2104.08,2217.17 2102.46,2217.17 2098.57,2221.06 P1.89@2098.57,2243.7 ; U2.2@1954.38,610.22 1974.21,610.22 1981.3,603.13 1981.3,594.53 1984.81,591.02 2039.47,591.02 2043.09,594.63 2048.04,594.63 2118.84,665.43 2183.65,665.43 ; v1@1981.66,594.18 v1(1984.58,597.1) ; R9.2@2238.93,590.09 2238.58,589.75 R7.1@2183.65,589.75 2183.65,665.43 ; J5.B02@2806.96,1350 2722.61,1350 2690.07,1317.45 2656.77,1317.45 2656.62,1317.3 2527.38,1317.3 2527.23,1317.45 2390.62,1317.45 2270.2,1197.03 2270.2,816.79 2183.65,730.24 2183.65,665.43
  Int2 (Sign) w6: v1(1877.2,1486.88) 1927.8,1486.88 1994.51,1420.17 1994.51,827 1988.76,821.25 2027.54,782.47 2027.54,696.08 1962.78,631.32 1962.78,625.97 1962.78,613.05 1969.1,606.73 1973.32,606.73 1982.95,597.1 v1(1984.58,597.1)
  Bottom Layer w6: v1(1877.2,1486.88) 1896.81,1486.88 R4.1@1898.89,1484.79 ; v1(1984.58,597.1) v1@1986.2,597.1
ADCIN2: J5.A02 P1.91 R5.1 R6.1 R8.2 U2.3 | length 3573.8
  Top Layer w6: v1(1877.49,1422.21) 2129.88,1422.21 ; U2.3@1954.38,625.97 v1@1975.43,625.97 ; v1(1977.78,625.11) 1996.25,606.63 2043.07,606.63 2258.2,821.76 2258.2,1202 2406.19,1350 J5.A02@2592,1350 ; P1.91@2122.19,2243.7 2122.19,2221.06 2126.08,2217.17 2126.36,2217.17 2129.88,2213.66 2129.88,1422.21 ; v1(2167.73,1422.15) 2167.67,1422.21 2129.88,1422.21 ; R6.1@2183.65,529.5 v1@2210.61,529.5 ; v1(2210.61,529.76) 2210.86,529.5 2238.58,529.5 R8.2@2238.93,529.85
  Int2 (Sign) w6: v1(1977.78,625.11) 1978.93,626.25 1978.93,630.5 2044.53,696.1 v1(2044.53,755.49)
  Bottom Layer w6: v1(1877.49,1422.21) 1890.73,1422.21 R5.1@1891.47,1421.47 ; v1(1977.78,625.11) 1995.45,642.78 2161.54,642.78 2210.61,593.71 v1(2210.61,529.76) ; v1(2044.53,755.49) 2044.86,755.82 2068.63,755.82 2169.18,856.36 2169.18,1407.81 2168.88,1408.1 2168.88,1421 v1(2167.73,1422.15)
C_CC1: J4.A5 R45.2 TP3.1 U12.4 | length 960.3
  Top Layer w8: U12.4@1757.53,399.3 1757.53,364.49 1757.78,364.24 1757.78,350.98 1757.62,350.82 1757.62,341.56
  Top Layer w10: J4.A5@1731.44,296.59 1731.75,296.9 1731.75,315.69 1757.62,341.56 1789.41,341.56 1790.77,342.91 v1(1818.67,342.91)
  Int2 (Sign) w6: TP3.1@1278.9,147.97 1298.92,147.97 1344.92,101.97 1543.22,101.97 1571.64,130.39 1769.14,130.39 1831.11,192.36 1831.11,329.9 1818.67,342.33 v1(1818.67,342.91)
  Bottom Layer w6: R45.2@1831.1,357.73 R45.2@1831.53,358.16
  Bottom Layer w10: v1(1818.67,342.91) 1819.05,343.3 1819.05,344.9 1831.1,356.95 R45.2@1831.1,357.73
C_CC2: J4.B5 R46.2 TP5.1 U12.5 | length 1100.2
  Top Layer w8: U12.5@1773.27,399.3 1773.27,368.74 1782.37,359.64 v1(1782.37,358.56)
  Top Layer w10: v1@1771.3,264.88 1771.3,264.34 1780.34,255.31 1780.34,233.91 J4.B5@1780.65,233.59
  Int2 (Sign) w6: TP5.1@1001,162 1015.03,162 1068.87,215.84 1493.85,215.84 1543.97,165.72 1720.78,165.72 1770.9,215.84 v1(1770.9,264.2)
  Int2 (Sign) w10: v1(1770.9,264.2) 1745.78,289.32 1745.78,321.43 1782.37,358.01 v1(1782.37,358.56)
  Bottom Layer w10: v1@1782.37,358.01 v1(1782.37,358.56) 1782.91,358.56 1783.81,357.65 1799.29,357.65 R46.2@1799.79,358.16
C_SBU1: J4.A8 U12.1 | length 178.3
  Top Layer w6: v1(1705.53,346.37) 1705.53,365.62 1710.28,370.38 U12.1@1710.28,399.3 ; J4.A8@1790.49,296.59 1791.16,297.26 1791.16,323.56 v1(1791.43,323.83) v1@1791.84,324.24
  Bottom Layer w6: v1(1705.53,346.37) 1729.68,346.37 1738.41,337.64 1777.61,337.64 v1(1791.43,323.83)
C_SBU2: J4.B8 U12.2 | length 209.5
  Top Layer w6: v1(1722.67,331.01) 1722.67,367.01 1726.03,370.37 U12.2@1726.03,399.3
  Top Layer w10: v1(1721.6,212.6) J4.B8@1721.6,233.59
  Int2 (Sign) w6: v1(1721.6,212.6) 1722.13,213.13 1722.13,330.47 v1(1722.67,331.01)
CC1: C52.1 J5.B05 P1.107 U2.24 U12.12 | length 2967.1
  Top Layer w6: v1(1757.53,594.22) v1@1757.65,594.35 ; C52.1@1773.02,594.35 C52.1@1773.15,594.48 ; v1(2268.93,719.9) 2268.93,758.91 2299.84,789.82 2299.84,1112.35 v1(2299.58,1112.61) 2706.75,1112.61 2769.36,1050 J5.B05@2806.96,1050 ; v1(2282.27,1344.2) 2249.02,1377.45 2249.02,1948.37 2311.16,2010.51 P1.107@2311.16,2243.7
  Top Layer w8: U12.12@1757.53,509.54 1757.53,517.29 1756.38,518.43 1756.38,551.35 1757.53,552.5 v1(1757.53,594.22) ; C52.1@1773.15,594.48 U2.24@1802.8,594.47
  Top Layer w10: v1@1757.65,594.35 C52.1@1773.02,594.35
  Int2 (Sign) w6: v1(1757.53,594.22) 1784.82,594.22 1814.77,564.27 1814.77,527.68 1835.59,506.87 1879.14,506.87 1894.14,491.87 2037.09,491.87 2040.61,495.38 2040.61,511.57 2052.43,523.4 2140.99,523.4 2244.58,626.99 2244.58,695.55 v1(2268.93,719.9) ; v1(2282.27,1344.2) 2299.58,1326.89 v1(2299.58,1112.61)
CC2: C51.1 J5.A05 P1.105 U2.25 U12.11 | length 2715.8
  Top Layer w6: v1(2222.98,1350) 2223.57,1350.58 2223.57,1974.79 2287.54,2038.77 P1.105@2287.54,2243.7 ; v1(2281.81,689.09) 2297.82,705.1 2297.82,752.38 2327.55,782.1 2327.55,913.87 2326.02,915.4 v1(2326.02,1048.91) 2588.74,1048.91 J5.A05@2589.83,1050
  Top Layer w8: U12.11@1773.27,509.54 1786.07,509.54 1791.07,514.54 1791.07,528.99 v1(1791.84,529.76) 1791.84,530.84 1795.98,534.99 C51.1@1795.98,539.55 ; C51.1@1795.98,544.25 1796.77,544.25 1799.07,546.55 1799.07,547.33 1818.71,566.97 U2.25@1823.41,566.97
  Int2 (Sign) w6: v1(1791.84,529.76) 1826.64,494.95 1833.07,494.95 1833.14,494.87 1874.17,494.87 1889.17,479.87 2205.68,479.87 2281.81,555.99 v1(2281.81,689.09)
  Bottom Layer w6: v1(2222.98,1350) 2222.98,1069.19 2243.26,1048.91 v1(2326.02,1048.91)
D2_N: U14.11 U22.43 | length 1160.4
  Bottom Layer w6: U22.43@443.94,1840.4 464.67,1840.4 468.51,1844.24 730.94,1844.24 737.97,1851.27 882.83,1996.13 946.8,1996.13 1031.12,2080.44 1031.12,2458.7 1005.39,2484.42 993.88,2484.42 984.13,2494.17 U14.11@968.76,2494.17 U14.11@950.29,2494.17
D2_P: U14.12 U22.44 | length 1105.9
  Bottom Layer w6: U22.44@443.94,1860.08 464.67,1860.08 468.51,1856.24 725.97,1856.24 877.86,2008.13 941.83,2008.13 1019.12,2085.41 1019.12,2453.72 1000.42,2472.42 993.88,2472.42 984.13,2462.67 U14.12@968.76,2462.67 U14.12@966.14,2465.29
D3_N: R89.2 U14.15 U19.2 | length 3226.8
  Top Layer w6: v1(1002.63,2368.19) 1001,2368.19 991.35,2358.53 832.82,2358.53 832.66,2358.37 829.15,2361.89 829.15,2363.25 826.24,2366.15 U19.2@823.29,2366.15 820.33,2366.15 815.23,2361.05 808.94,2361.05 805.62,2364.37 766.76,2364.37 761.04,2358.66 675.41,2358.66 629.44,2312.68 594.81,2312.68 440.47,2158.35 440.47,478.24 663.88,254.82 677.85,240.86 1119.39,240.86 1145.68,267.15 1145.68,291.86 1149.2,295.38 1150.38,295.38 1153.68,298.68 R89.2@1153.68,299.47
  Bottom Layer w6: U14.15@970.89,2366.05 U14.15@968.76,2368.19 v1(1002.63,2368.19)
D3_P: R90.2 U14.16 U19.1 | length 3164.9
  Top Layer w6: v1@1003.37,2334.9 991.73,2346.53 832.82,2346.53 829.15,2342.86 829.15,2341.5 826.24,2338.59 U19.1@823.29,2338.59 820.33,2338.59 815.23,2343.7 808.94,2343.7 805.62,2340.37 766.76,2340.37 760.48,2346.66 680.39,2346.66 634.41,2300.68 599.78,2300.68 452.47,2153.38 452.47,483.21 672.37,263.31 682.82,252.86 1114.42,252.86 1133.68,272.12 1133.68,291.86 1130.17,295.38 1128.98,295.38 1125.68,298.68 R90.2@1125.68,299.47
  Bottom Layer w6: U14.16@968.76,2336.69 v1(1001.58,2336.69)
D_N: J6.A7 J6.B7 U14.2 U15.2 | length 391.1
  Bottom Layer w6: U15.2@726.95,2696.23 726.95,2693.27 729.85,2690.37 730.28,2690.37 733.8,2686.85 733.8,2648.95 727.62,2642.77 U14.2@727.62,2609.33 ; U15.2@726.95,2699.18 724.04,2702.09 722.68,2702.09 719.17,2705.6 719.17,2713.44 722.68,2716.96 811.09,2716.96 821.63,2727.5 821.63,2830.47 818.12,2833.98 798.87,2833.98 792.11,2840.75 J6.B7@792.11,2875.93
D_P: J6.A6 J6.B6 R53.1 U14.1 U15.1 | length 495.4
  Int2 (Sign) w6: v1(801.92,2777.65) 801.92,2880.94 811.96,2890.98 v1(811.96,2892.11)
  Bottom Layer w6: R53.1@629.7,2609.52 629.9,2609.33 U14.1@696.12,2609.33 696.12,2690.01 699.39,2693.27 U15.1@699.39,2696.23 699.39,2699.18 702.29,2702.09 703.65,2702.09 707.17,2705.6 707.17,2718.41 717.71,2728.96 806.12,2728.96 809.63,2732.47 809.63,2769.94 v1(801.92,2777.65) ; v1@801.93,2777.67 J6.A6@801.93,2790.09 ; J6.B6@811.79,2865.5 811.88,2865.58 811.88,2892.02 v1(811.96,2892.11)
DBG_UART: P1.29 U22.17 | length 1243.8
  Top Layer w6: v1(813.48,1619.2) 814,1619.72 1378.91,1619.72 v1(1379.43,1620.25) ; v1(1388.12,2147.04) 1389.01,2147.93 1389.01,2242.81 P1.29@1389.9,2243.7
  Bottom Layer w6: U22.17@813.04,1569.73 813.26,1569.95 813.26,1618.98 v1(813.48,1619.2) ; v1(1379.43,1620.25) 1379.43,2136.72 1388.12,2145.41 v1(1388.12,2147.04)
EXP_D_N: P1.4 U14.19 U18.2 | length 636
  Top Layer w6: v1(913.39,2140.36) 914.54,2139.21 920.75,2139.21 921.1,2138.86 944.36,2138.86 1022.59,2217.09 1022.59,2324.58 1088.63,2390.61 1088.63,2427.85 1082.82,2433.66 P1.4@1082.82,2456.3
  Bottom Layer w6: U14.19@853.6,2284.52 853.6,2269.15 843.85,2259.4 843.85,2252.86 844.03,2252.68 844.03,2237.84 847.54,2234.32 848.9,2234.32 851.81,2231.42 U18.2@851.81,2228.47 851.81,2173.72 844.03,2165.94 844.03,2144.69 851.36,2137.36 908.76,2137.36 911.76,2140.36 v1(913.39,2140.36)
EXP_D_P: P1.6 U14.20 U18.1 | length 674.5
  Top Layer w6: v1(913.39,2125.36) 914.54,2126.51 920.75,2126.51 921.1,2126.86 949.33,2126.86 1034.59,2212.12 1034.59,2319.61 1100.63,2385.64 1100.63,2427.85 1106.44,2433.66 P1.6@1106.44,2456.3
  Bottom Layer w6: U14.20@822.11,2284.52 822.11,2269.15 831.85,2259.4 831.85,2247.89 832.03,2247.71 832.03,2237.84 828.52,2234.32 827.16,2234.32 824.25,2231.42 U18.1@824.25,2228.47 824.25,2173.72 832.03,2165.94 832.03,2139.71 846.39,2125.36 v1(913.39,2125.36)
